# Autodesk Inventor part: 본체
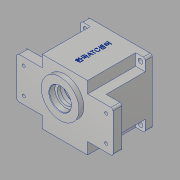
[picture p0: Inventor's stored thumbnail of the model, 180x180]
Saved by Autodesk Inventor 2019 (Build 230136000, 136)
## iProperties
Created: 2020-01
Part Number: 본체
Material: 알루미늄 6061
Document SubType Name: Modeling
Designer: 323-3
Density: 2.7 g/cm^3
Appearance: 알루미늄 - 평지
Mass: 876.486 g
Surface Area: 793.573 cm^2
Volume: 324.624 cm^3
Author: 323-3
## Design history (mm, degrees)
sketch "스케치4"
  geometry: L1 (47, -47)-(-47, -47); L2 (-47, -47)-(-47, 47); L3 (-47, 47)-(47, 47); L4 (47, 47)-(47, -47); L5 (47, -47)-(-47, 47); L6 (-47, -47)-(47, 47); 1 further point
  constraints: 12 end point, 2 midpoint, 2 parallel, 1 horizontal, 1 perpendicular
  dimensions: "d11" = 94 distance of L2.end L3.end; "d12" = 94 distance of L1.end L2.end
extrude "돌출4" new body sketch "스케치4" distance "d13" = 80; taper "d14" = 0 deg
sketch "스케치5"
  geometry: L1 (70, -30)-(-70, -30); L2 (-70, -30)-(-70, 30); L3 (-70, 30)-(70, 30); L4 (70, 30)-(70, -30); L5 (70, -30)-(-70, 30); L6 (-70, -30)-(70, 30); 1 further point
  constraints: 12 end point, 2 midpoint, 2 parallel, 1 horizontal, 1 perpendicular
  dimensions: "d15" = 140 distance of L2.end L3.end; "d16" = 60 distance of L1.end L2.end
extrude "돌출5" join sketch "스케치5" distance "d17" = 13; taper "d18" = 0 deg
sketch "스케치6"
  geometry: C1 r 40 at (0, 0); 1 further point
  constraints: 1 centre point, 1 coincident
  dimensions: "d19" = 80 diameter of C1
extrude "돌출6" cut sketch "스케치6" distance "d20" = 71; taper "d21" = 0 deg
sketch "스케치7"
  geometry: C1 r 21 at (0, 11); C2 r 15 at (0, -20); 1 further point
  constraints: 2 centre point, 2 vertical alignment
  dimensions: "d22" = 42 diameter of C1; "d23" = 11 distance of point (0, 0) C1.centre; "d24" = 30 diameter of C2; "d25" = 20 distance of C2.centre point (0, 0)
extrude "돌출7" join sketch "스케치7" distance "d26" = 7; taper "d27" = 0 deg
fillet "모깎기1" dims "d28" = 3
sketch "스케치8"
  geometry: C1 r 17.5 at (0, 11); A1 r 21 centre (0, 11) between (12.163, -6.119) and (-12.163, -6.119) reference; A2 r 3 centre (-13.901, -8.565) between (-11.584, -10.47) and (-12.163, -6.119) reference; A3 r 15 centre (0, -20) between (-11.584, -10.47) and (11.584, -10.47) reference; A4 r 3 centre (13.901, -8.565) between (12.163, -6.119) and (11.584, -10.47) reference; 1 further point
  constraints: 1 centre point, 1 coincident
  dimensions: "d29" = 35 diameter of C1
extrude "돌출8" cut sketch "스케치8" distance "d30" = 10; taper "d31" = 0 deg
sketch "스케치9"
  geometry: C1 r 17.5 at (0, 11) reference; C2 r 11 at (0, -20); A1 r 21 centre (0, 11) between (12.163, -6.119) and (-12.163, -6.119) reference; A2 r 3 centre (-13.901, -8.565) between (-11.584, -10.47) and (-12.163, -6.119) reference; A3 r 15 centre (0, -20) between (-11.584, -10.47) and (11.584, -10.47) reference; A4 r 3 centre (13.901, -8.565) between (12.163, -6.119) and (11.584, -10.47) reference; 1 further point
  constraints: 1 centre point, 1 coincident
  dimensions: "d32" = 22 diameter of C2
extrude "돌출9" cut sketch "스케치9" distance "d33" = 7; taper "d34" = 0 deg
sketch "스케치10"
  geometry: C1 r 11 at (0, 0) reference; C2 r 9.5 at (0, 0); 1 further point
  constraints: 1 centre point, 1 coincident
  dimensions: "d35" = 19 diameter of C2
extrude "돌출10" cut sketch "스케치10" distance "d36" = 3; taper "d37" = 0 deg
chamfer "모따기1" distance "d38" = 1; stored, may be unused: second distance "d39" = 2, angle "d40" = 45 deg
sketch "스케치11"
  geometry: C1 r 27.5 at (0, 11); 1 further point
  constraints: 1 centre point, 1 vertical alignment
  dimensions: "d41" = 55 diameter of C1; "d42" = 11 distance of point (0, 0) C1.centre
extrude "돌출11" join sketch "스케치11" distance "d43" = 7; taper "d44" = 0 deg
sketch "스케치12"
  geometry: C1 r 27.5 at (0, 0) reference; C2 r 16 at (0, 0); 1 further point
  constraints: 1 centre point, 1 coincident
  dimensions: "d45" = 32 diameter of C2
extrude "돌출12" cut sketch "스케치12" distance "d46" = 8.3; taper "d47" = 0 deg
sketch "스케치13"
  geometry: C1 r 16 at (0, 0) reference; C2 r 12.5 at (0, 0); 1 further point
  constraints: 1 centre point, 1 coincident
  dimensions: "d48" = 25 diameter of C2
extrude "돌출13" cut sketch "스케치13" distance "d49" = 9.2; taper "d50" = 0 deg
chamfer "모따기2" distance "d51" = 0.8; stored, may be unused: second distance "d52" = 2, angle "d53" = 30 deg
fillet "모깎기2" dims "d54" = 3
sketch "스케치14"
  geometry: C1 r 43 at (0, 0); 1 further point
  constraints: 1 centre point, 1 coincident
  dimensions: "d55" = 86 diameter of C1
extrude "돌출14" cut sketch "스케치14" distance "d56" = 9; taper "d57" = 0 deg
chamfer "모따기3" distance "d58" = 1; stored, may be unused: second distance "d59" = 2, angle "d60" = 30 deg
sketch "스케치15" dims "d61" = 72
  geometry: L1 (36, 4)-(39.799, 4); L2 (36, -4)-(39.799, -4); A1 r 4 centre (36, 0) between (36, 4) and (36, -4); A2 r 40 centre (0, 0) between (39.799, 4) and (39.799, -4) reference; A3 r 4 centre (36, 0) between (40, 0) and (36, 4); A4 r 4 centre (36, 0) between (36, -4) and (40, 0); 2 further points
  constraints: 9 point on circle, 4 end point, 4 tangent, 3 centre point, 2 horizontal, 2 horizontal alignment, 1 coincident, 2 other
  dimensions: "d62" = 8 diameter of A1
extrude "돌출15" join sketch "스케치15" stored distance "d63" = 9; taper "d64" = 0 deg
fillet "모깎기3" dims "d65" = 3
sketch "스케치16"
  geometry: A1 r 4 centre (36, 0) between (36, 4) and (36, -4) reference; 2 further points
  constraints: 1 coincident
hole "구멍1" sketch "스케치16" at (36, 0) diameter "d66" = 3.242; stored, may be unused: countersink angle "d70" = 90 deg, drill point angle "d72" = 118 deg; dims "d67" = 7, "d68" = 4, "d69" = 2, "d71" = 9
sketch "스케치18"
  geometry: C1 r 5 at (-60, 19); 1 further point
  constraints: 1 centre point
  dimensions: "d74" = 10 diameter of C1; "d75" = 60 horizontal distance of C1.centre point (0, 0); "d76" = 19 vertical distance of C1.centre point (0, 0)
hole "구멍2" sketch "스케치18" at (-60, 19) diameter "d77" = 4.5; stored, may be unused: countersink angle "d81" = 90 deg, drill point angle "d83" = 118 deg; dims "d78" = 7, "d79" = 10, "d80" = 5, "d82" = 9
sketch "스케치19"
  geometry: L1 (47, 47)-(47, 30) reference; L2 (47, 47)-(33, 47); L3 (33, 47)-(33, 30); L4 (33, 30)-(47, 30); L5 (47, 30)-(47, 47); 1 further point
  constraints: 8 end point, 2 parallel, 1 horizontal, 1 perpendicular
  dimensions: "d84" = 33 distance from line of L3 point (0, 0); "d85" = 30 distance from line of point (0, 0) L4
extrude "돌출16" cut sketch "스케치19" distance "d86" = 70; taper "d87" = 0 deg
sketch "스케치20"
  geometry: C1 r 3.5 at (40, 40); 1 further point
  constraints: 1 centre point
  dimensions: "d88" = 7 diameter of C1; "d89" = 40 horizontal distance of C1.centre point (0, 0); "d90" = 40 horizontal distance of C1.centre point (0, 0)
extrude "돌출17" cut sketch "스케치20" distance "d91" = 70; taper "d92" = 0 deg
fillet "모깎기4" dims "d93" = 3
fillet "모깎기5" dims "d94" = 3
sketch "스케치21"
  geometry: L1 (-77, 80)-(11, 80) reference; 2 further points
  constraints: 1 other
  dimensions: "d97" = 40 distance from line of L1 point (-31.479, 40)
feature "엠보싱1" sketch "스케치21" dims "d95" = 0.5, "d96" = 0
node "솔리드2"
mirror "미러1"
mirror "미러2"
mirror "미러3"
mirror "미러4"
mirror "미러5"
mirror "미러6"
mirror "미러7"
mirror "미러8"
node "투영된 루프1"
node "투영된 루프2"
node "투영된 루프3"
node "투영된 루프4"
node "투영된 루프5"
